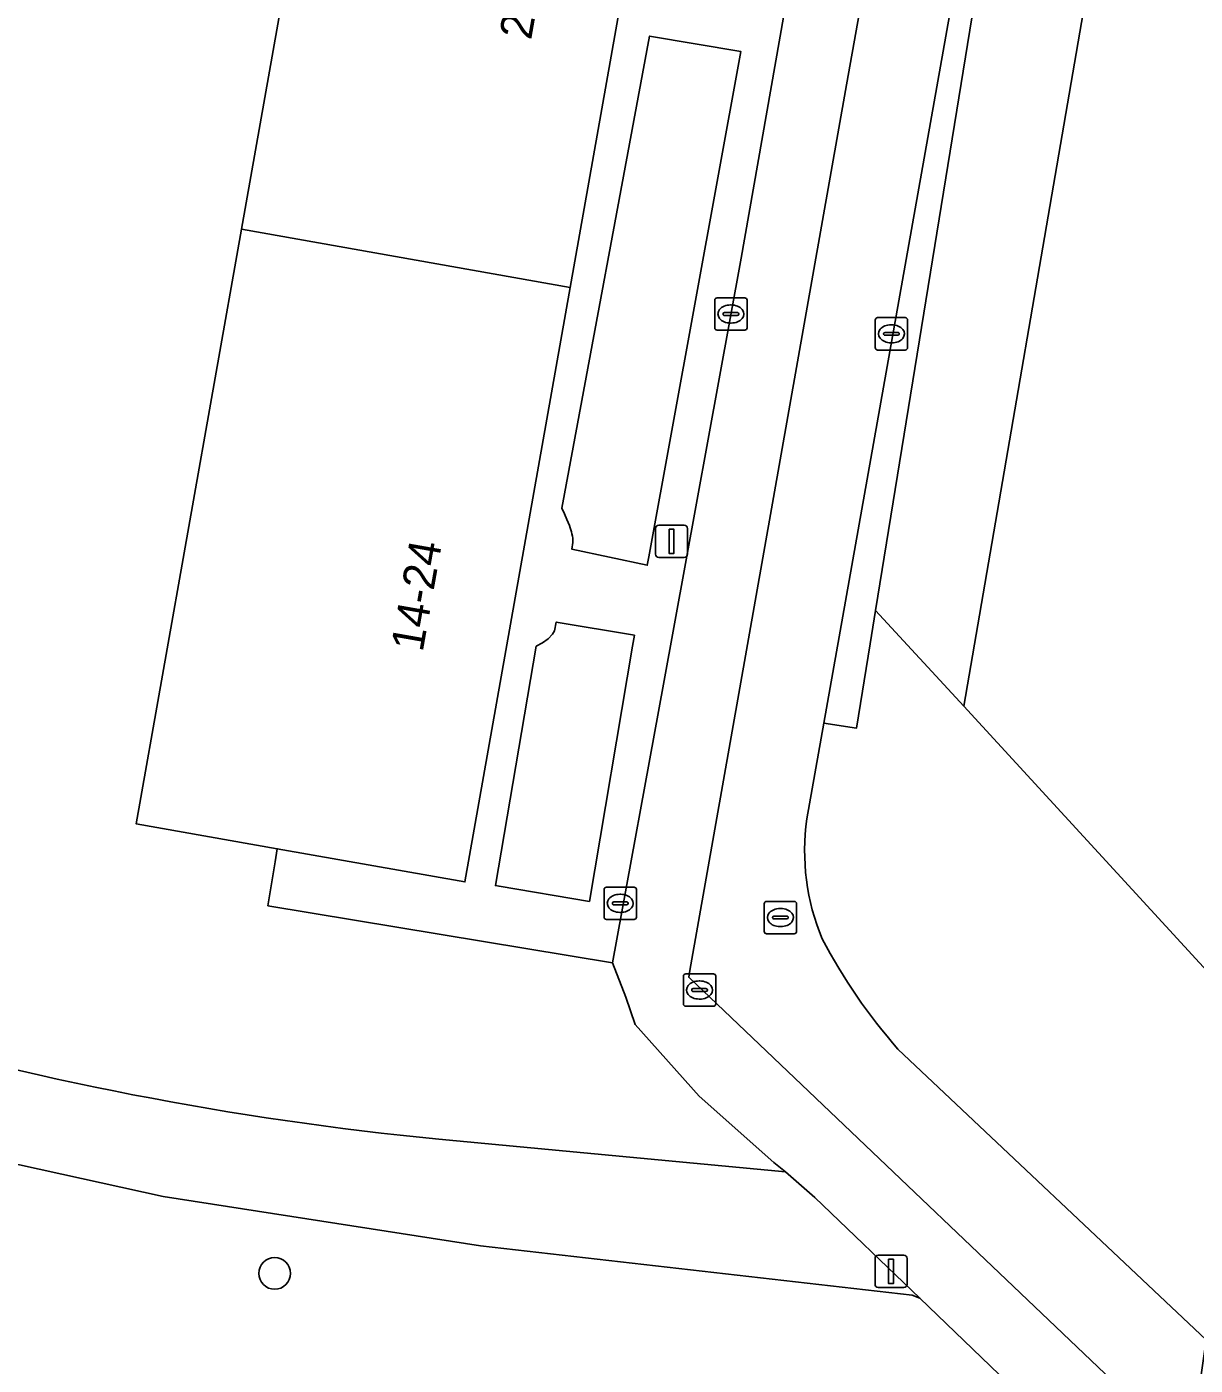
# Model space of a CAD drawing. Extents: x 161402 to 161933, y 381647 to 382315.
# Drawn here: x 161750.87 to 161786.96, y 381873.54 to 381914.91 of the extents above; entities that cross this region are included whole.
import ezdxf

# ---------------------------------------------------------------- set-up
doc = ezdxf.new("R2010")
doc.units = 0
for name, color, linetype in [('IMGEO_Boom', 7, 'Continuous'), ('IMGEO_Groenvoorziening', 7, 'Continuous'), ('IMGEO_Haag', 7, 'Continuous'), ('IMGEO_Kolk', 7, 'Continuous'), ('IMGEO_Lichtmast', 7, 'Continuous'), ('IMGEO_Pand', 7, 'Continuous'), ('IMGEO_Pand_nummerreeks', 7, 'Continuous'), ('IMGEO_Parkeervlak_open', 7, 'Continuous'), ('IMGEO_Rijbaan_lokaal_open', 7, 'Continuous'), ('IMGEO_Rioolput', 7, 'Continuous'), ('IMGEO_Voetpad_gesloten', 7, 'Continuous'), ('IMGEO_Voetpad_open', 7, 'Continuous')]:
    doc.layers.add(name, color=color, linetype=linetype)

msp = doc.modelspace()

# ---------------------------------------------------------------- linework, layer by layer
at = {"layer": 'IMGEO_Boom'}
msp.add_circle((161758.532, 381876.381), 0.489, dxfattribs=at)
at = {"layer": 'IMGEO_Groenvoorziening'}
for points in [[(161794.921, 381938.465), (161786.816, 381934.618), (161779.814, 381893.915), (161788.716, 381884.216), (161790.718, 381897.39), (161795.348, 381935.098)], [(161768.961, 381885.978), (161758.322, 381887.744), (161758.545, 381889.099), (161758.611, 381889.504), (161754.257, 381890.274), (161757.508, 381908.649), (161760.759, 381927.025), (161770.911, 381925.228), (161771.029, 381925.951), (161771.159, 381926.744), (161771.362, 381926.92), (161776.174, 381926.042), (161776.84, 381929.749), (161763.83, 381931.916), (161761.561, 381932.294), (161753.635, 381933.615), (161746.013, 381890.587), (161744.878, 381884.178)], [(161772.929, 381914.138), (161770.112, 381914.616), (161767.404, 381900.027), (161767.48, 381899.856), (161767.556, 381899.683), (161767.635, 381899.489)], [(161767.745, 381898.97), (161767.706, 381898.766), (161770.039, 381898.265), (161770.086, 381898.523), (161772.929, 381914.138)], [(161779.814, 381893.915), (161777.092, 381896.872), (161776.924, 381895.837), (161776.5, 381893.226), (161775.497, 381893.39), (161774.971, 381890.426)], [(161777.78, 381883.315), (161787.303, 381874.33), (161787.345, 381874.628), (161788.716, 381884.216), (161779.814, 381893.915)], [(161763.6, 381880.53), (161774.308, 381879.519), (161773.952, 381879.809), (161771.638, 381881.858), (161769.662, 381884.07), (161769.381, 381884.923), (161768.961, 381885.978)]]:
    msp.add_lwpolyline(points, dxfattribs=at)
for points in [[(161782.918, 381932.741), (161783.2, 381934.478), (161782.784, 381934.462), (161775.497, 381893.39), (161776.5, 381893.226), (161776.924, 381895.837), (161777.092, 381896.872)], [(161779.814, 381893.915), (161786.816, 381934.618), (161782.918, 381932.741), (161777.092, 381896.872)], [(161769.643, 381896.103), (161767.228, 381896.511), (161767.174, 381896.24), (161767.115, 381896.132), (161766.978, 381895.991), (161766.803, 381895.872), (161766.609, 381895.764), (161765.347, 381888.366), (161765.464, 381888.346), (161768.253, 381887.875), (161769.585, 381895.761)], [(161778.453, 381875.613), (161778.225, 381875.706), (161764.885, 381877.23), (161755.085, 381878.76), (161745.595, 381880.853), (161744.038, 381871.1), (161758.643, 381868.683), (161758.758, 381869.329), (161762.157, 381868.723), (161762.42, 381870.235), (161785.953, 381866.129), (161786.294, 381868.013), (161785.266, 381869.061)]]:
    msp.add_lwpolyline(points, close=True, dxfattribs=at)
for centre, radius, start, end in [((161766.287, 381898.932), 1.458, 1.4862, 22.4469), ((161781.898, 381889.424), 6.999, 171.766, 202.7426), ((161791.369, 381895.151), 18.022, 207.9024, 221.056), ((161773.213, 381979.731), 99.666, 253.48297, 264.46507)]:
    msp.add_arc(centre, radius, start, end, dxfattribs=at)
at = {"layer": 'IMGEO_Haag'}
msp.add_lwpolyline([(161782.918, 381932.741), (161783.2, 381934.478), (161782.784, 381934.462), (161775.497, 381893.39), (161776.5, 381893.226), (161776.924, 381895.837), (161777.092, 381896.872)], close=True, dxfattribs=at)
at = {"layer": 'IMGEO_Kolk'}
for p, q in [((161772.122, 381905.603), (161772.122, 381906.455)), ((161772.197, 381906.529), (161773.049, 381906.529)), ((161772.61, 381906.309), (161772.635, 381906.309)), ((161773.123, 381906.455), (161773.123, 381905.603)), ((161772.381, 381906.023), (161772.381, 381906.035)), ((161772.819, 381905.986), (161772.421, 381905.986)), ((161772.424, 381906.072), (161772.822, 381906.072)), ((161772.865, 381906.035), (161772.865, 381906.023)), ((161777.155, 381905.916), (161778.007, 381905.916)), ((161773.049, 381905.529), (161772.197, 381905.529)), ((161772.633, 381905.749), (161772.608, 381905.749)), ((161777.08, 381904.99), (161777.08, 381905.842)), ((161777.382, 381905.459), (161777.78, 381905.459)), ((161777.568, 381905.696), (161777.593, 381905.696)), ((161778.081, 381905.842), (161778.081, 381904.99)), ((161777.339, 381905.41), (161777.339, 381905.422)), ((161777.777, 381905.373), (161777.379, 381905.373)), ((161777.591, 381905.136), (161777.566, 381905.136)), ((161777.823, 381905.422), (161777.823, 381905.41)), ((161778.007, 381904.916), (161777.155, 381904.916)), ((161768.704, 381887.392), (161768.704, 381888.244)), ((161768.779, 381888.318), (161769.631, 381888.318)), ((161769.192, 381888.098), (161769.217, 381888.098)), ((161769.705, 381888.244), (161769.705, 381887.392)), ((161768.963, 381887.812), (161768.963, 381887.824)), ((161769.401, 381887.775), (161769.003, 381887.775)), ((161769.006, 381887.861), (161769.404, 381887.861)), ((161769.447, 381887.824), (161769.447, 381887.812)), ((161773.651, 381886.952), (161773.651, 381887.804)), ((161773.726, 381887.878), (161774.578, 381887.878)), ((161774.652, 381887.804), (161774.652, 381886.952)), ((161769.631, 381887.318), (161768.779, 381887.318)), ((161769.215, 381887.538), (161769.19, 381887.538)), ((161773.91, 381887.372), (161773.91, 381887.384)), ((161774.348, 381887.335), (161773.95, 381887.335)), ((161773.953, 381887.421), (161774.351, 381887.421)), ((161774.139, 381887.658), (161774.164, 381887.658)), ((161774.394, 381887.384), (161774.394, 381887.372)), ((161774.578, 381886.878), (161773.726, 381886.878)), ((161774.162, 381887.098), (161774.137, 381887.098))]:
    msp.add_line(p, q, dxfattribs=at)
for points in [[(161772.122, 381905.603), (161772.122, 381906.455)], [(161772.197, 381906.529), (161773.049, 381906.529)], [(161773.123, 381906.455), (161773.123, 381905.603)], [(161777.155, 381905.916), (161778.007, 381905.916)], [(161773.049, 381905.529), (161772.197, 381905.529)], [(161777.08, 381904.99), (161777.08, 381905.842)], [(161778.081, 381905.842), (161778.081, 381904.99)], [(161778.007, 381904.916), (161777.155, 381904.916)], [(161768.704, 381887.392), (161768.704, 381888.244)], [(161768.779, 381888.318), (161769.631, 381888.318)], [(161769.705, 381888.244), (161769.705, 381887.392)], [(161773.651, 381886.952), (161773.651, 381887.804)], [(161773.726, 381887.878), (161774.578, 381887.878)], [(161774.652, 381887.804), (161774.652, 381886.952)], [(161769.631, 381887.318), (161768.779, 381887.318)], [(161774.578, 381886.878), (161773.726, 381886.878)]]:
    msp.add_lwpolyline(points, dxfattribs=at)
for centre, radius, start, end in [((161772.199, 381906.453), 0.0765, 91.552, 178.448), ((161772.199, 381906.453), 0.0765, 91.552, 178.448), ((161773.047, 381906.453), 0.0765, 1.552, 88.448), ((161773.047, 381906.453), 0.0765, 1.552, 88.448), ((161772.421, 381906.032), 0.0403, 85.8775, 175.7526), ((161772.418, 381906.022), 0.0366, 178.938, 274.7102), ((161772.822, 381906.029), 0.043, 264.8664, 352.4533), ((161772.826, 381906.034), 0.0386, 1.7309, 96.639), ((161777.157, 381905.84), 0.0765, 91.552, 178.448), ((161777.157, 381905.84), 0.0765, 91.552, 178.448), ((161778.005, 381905.84), 0.0765, 1.552, 88.448), ((161778.005, 381905.84), 0.0765, 1.552, 88.448), ((161772.199, 381905.605), 0.0765, 181.552, 268.448), ((161772.199, 381905.605), 0.0765, 181.552, 268.448), ((161773.047, 381905.605), 0.0765, 271.552, 358.448), ((161773.047, 381905.605), 0.0765, 271.552, 358.448), ((161777.379, 381905.419), 0.0403, 85.8775, 175.7526), ((161777.784, 381905.421), 0.0386, 1.7309, 96.639), ((161777.376, 381905.409), 0.0366, 178.938, 274.7102), ((161777.78, 381905.416), 0.043, 264.8664, 352.4533), ((161777.157, 381904.992), 0.0765, 181.552, 268.448), ((161777.157, 381904.992), 0.0765, 181.552, 268.448), ((161778.005, 381904.992), 0.0765, 271.552, 358.448), ((161778.005, 381904.992), 0.0765, 271.552, 358.448), ((161768.781, 381888.242), 0.0765, 91.552, 178.448), ((161768.781, 381888.242), 0.0765, 91.552, 178.448), ((161769.629, 381888.242), 0.0765, 1.552, 88.448), ((161769.629, 381888.242), 0.0765, 1.552, 88.448), ((161769.003, 381887.821), 0.0403, 85.8775, 175.7526), ((161769, 381887.811), 0.0366, 178.938, 274.7102), ((161769.404, 381887.818), 0.043, 264.8664, 352.4533), ((161769.408, 381887.823), 0.0386, 1.7309, 96.639), ((161773.728, 381887.802), 0.0765, 91.552, 178.448), ((161773.728, 381887.802), 0.0765, 91.552, 178.448), ((161774.576, 381887.802), 0.0765, 1.552, 88.448), ((161774.576, 381887.802), 0.0765, 1.552, 88.448), ((161768.781, 381887.394), 0.0765, 181.552, 268.448), ((161768.781, 381887.394), 0.0765, 181.552, 268.448), ((161769.629, 381887.394), 0.0765, 271.552, 358.448), ((161769.629, 381887.394), 0.0765, 271.552, 358.448), ((161773.95, 381887.381), 0.0403, 85.8775, 175.7526), ((161773.947, 381887.371), 0.0366, 178.938, 274.7102), ((161774.351, 381887.378), 0.043, 264.8664, 352.4533), ((161774.355, 381887.383), 0.0386, 1.7309, 96.639), ((161773.728, 381886.954), 0.0765, 181.552, 268.448), ((161773.728, 381886.954), 0.0765, 181.552, 268.448), ((161774.576, 381886.954), 0.0765, 271.552, 358.448), ((161774.576, 381886.954), 0.0765, 271.552, 358.448)]:
    msp.add_arc(centre, radius, start, end, dxfattribs=at)
for centre, major_axis, ratio, start_param, end_param in [((161772.609, 381906.029), (-0.387, 0.002), 0.722429, 4.712389, 7.853982), ((161772.634, 381906.029), (-0.39, 0.002), 0.717154, 1.570796, 4.712389), ((161777.567, 381905.416), (-0.387, 0.002), 0.722429, 4.712389, 7.853982), ((161777.592, 381905.416), (-0.39, 0.002), 0.717154, 1.570796, 4.712389), ((161769.191, 381887.818), (-0.387, 0.002), 0.722429, 4.712389, 7.853982), ((161769.216, 381887.818), (-0.39, 0.002), 0.717154, 1.570796, 4.712389), ((161774.138, 381887.378), (-0.387, 0.002), 0.722429, 4.712389, 7.853982), ((161774.163, 381887.378), (-0.39, 0.002), 0.717154, 1.570796, 4.712389)]:
    msp.add_ellipse(centre, major_axis=major_axis, ratio=ratio, start_param=start_param, end_param=end_param, dxfattribs=at)
at = {"layer": 'IMGEO_Lichtmast'}
for p, q in [((161770.292, 381898.604), (161770.292, 381899.404)), ((161770.292, 381899.404), (161770.292, 381898.604)), ((161770.392, 381899.504), (161771.182, 381899.504)), ((161771.182, 381899.504), (161770.392, 381899.504)), ((161771.282, 381899.404), (161771.282, 381898.604)), ((161771.282, 381898.604), (161771.282, 381899.404)), ((161771.182, 381898.504), (161770.392, 381898.504)), ((161770.392, 381898.504), (161771.182, 381898.504)), ((161777.173, 381876.944), (161777.963, 381876.944)), ((161777.963, 381876.944), (161777.173, 381876.944)), ((161777.073, 381876.044), (161777.073, 381876.844)), ((161777.073, 381876.844), (161777.073, 381876.044)), ((161778.063, 381876.844), (161778.063, 381876.044)), ((161778.063, 381876.044), (161778.063, 381876.844)), ((161777.963, 381875.944), (161777.173, 381875.944)), ((161777.173, 381875.944), (161777.963, 381875.944))]:
    msp.add_line(p, q, dxfattribs=at)
for points in [[(161770.712, 381899.379), (161770.862, 381899.379), (161770.862, 381898.629), (161770.712, 381898.629), (161770.712, 381899.379)], [(161777.493, 381876.819), (161777.643, 381876.819), (161777.643, 381876.069), (161777.493, 381876.069), (161777.493, 381876.819)]]:
    msp.add_lwpolyline(points, dxfattribs=at)
for centre, start, end in [((161770.392, 381899.404), 90, 180), ((161770.392, 381899.404), 90, 180), ((161771.182, 381899.404), 0, 90), ((161771.182, 381899.404), 360, 90), ((161770.392, 381898.604), 180, 270), ((161770.392, 381898.604), 180, 270), ((161771.182, 381898.604), 270, 0), ((161771.182, 381898.604), 270, 0), ((161777.173, 381876.844), 90, 180), ((161777.173, 381876.844), 90, 180), ((161777.963, 381876.844), 0, 90), ((161777.963, 381876.844), 360, 90), ((161777.173, 381876.044), 180, 270), ((161777.173, 381876.044), 180, 270), ((161777.963, 381876.044), 270, 0), ((161777.963, 381876.044), 270, 0)]:
    msp.add_arc(centre, 0.1, start, end, dxfattribs=at)
at = {"layer": 'IMGEO_Pand'}
for points in [[(161757.508, 381908.649), (161767.659, 381906.853), (161770.911, 381925.228), (161760.759, 381927.025)], [(161757.508, 381908.649), (161754.257, 381890.274), (161758.611, 381889.504), (161764.408, 381888.478), (161767.659, 381906.853)]]:
    msp.add_lwpolyline(points, close=True, dxfattribs=at)
at = {"layer": 'IMGEO_Parkeervlak_open'}
msp.add_lwpolyline([(161786.796, 381870.79), (161771.319, 381885.533), (161771.355, 381885.738), (161776.189, 381913.114), (161778.071, 381923.6), (161775.809, 381923.999), (161774.646, 381917.502), (161772.935, 381907.756), (161770.541, 381894.588), (161768.961, 381885.978), (161769.381, 381884.923), (161769.662, 381884.07), (161771.638, 381881.858), (161773.952, 381879.809), (161774.308, 381879.519), (161775.214, 381878.728), (161778.453, 381875.613), (161785.266, 381869.061), (161786.294, 381868.013)], close=True, dxfattribs=at)
at = {"layer": 'IMGEO_Rijbaan_lokaal_open'}
for points in [[(161782.784, 381934.462), (161784.762, 381945.37), (161780.082, 381947.784), (161779.9, 381946.775), (161782.071, 381946.391), (161778.29, 381924.974), (161776.054, 381925.369), (161775.809, 381923.999), (161778.071, 381923.6), (161776.189, 381913.114), (161771.355, 381885.738), (161771.319, 381885.533), (161786.796, 381870.79), (161787.303, 381874.33), (161777.78, 381883.315)], [(161774.971, 381890.426), (161775.497, 381893.39), (161782.784, 381934.462)]]:
    msp.add_lwpolyline(points, dxfattribs=at)
for centre, radius, start, end in [((161781.898, 381889.424), 6.999, 171.766, 202.7426), ((161791.369, 381895.151), 18.022, 207.9024, 221.056)]:
    msp.add_arc(centre, radius, start, end, dxfattribs=at)
at = {"layer": 'IMGEO_Rioolput'}
for p, q in [((161771.228, 381885.639), (161772.08, 381885.639)), ((161771.153, 381884.713), (161771.153, 381885.565)), ((161771.455, 381885.182), (161771.853, 381885.182)), ((161771.641, 381885.419), (161771.666, 381885.419)), ((161772.154, 381885.565), (161772.154, 381884.713)), ((161771.412, 381885.133), (161771.412, 381885.145)), ((161771.85, 381885.096), (161771.452, 381885.096)), ((161771.664, 381884.859), (161771.639, 381884.859)), ((161771.896, 381885.145), (161771.896, 381885.133)), ((161772.08, 381884.639), (161771.228, 381884.639))]:
    msp.add_line(p, q, dxfattribs=at)
for points in [[(161771.228, 381885.639), (161772.08, 381885.639)], [(161771.153, 381884.713), (161771.153, 381885.565)], [(161772.154, 381885.565), (161772.154, 381884.713)], [(161772.08, 381884.639), (161771.228, 381884.639)]]:
    msp.add_lwpolyline(points, dxfattribs=at)
for centre, radius, start, end in [((161771.23, 381885.563), 0.0765, 91.552, 178.448), ((161771.23, 381885.563), 0.0765, 91.552, 178.448), ((161772.078, 381885.563), 0.0765, 1.552, 88.448), ((161772.078, 381885.563), 0.0765, 1.552, 88.448), ((161771.452, 381885.142), 0.0403, 85.8775, 175.7526), ((161771.857, 381885.144), 0.0386, 1.7309, 96.639), ((161771.449, 381885.132), 0.0366, 178.938, 274.7102), ((161771.853, 381885.139), 0.043, 264.8664, 352.4533), ((161771.23, 381884.715), 0.0765, 181.552, 268.448), ((161771.23, 381884.715), 0.0765, 181.552, 268.448), ((161772.078, 381884.715), 0.0765, 271.552, 358.448), ((161772.078, 381884.715), 0.0765, 271.552, 358.448)]:
    msp.add_arc(centre, radius, start, end, dxfattribs=at)
for centre, major_axis, ratio, start_param, end_param in [((161771.64, 381885.139), (-0.387, 0.002), 0.722429, 4.712389, 7.853982), ((161771.665, 381885.139), (-0.39, 0.002), 0.717154, 1.570796, 4.712389)]:
    msp.add_ellipse(centre, major_axis=major_axis, ratio=ratio, start_param=start_param, end_param=end_param, dxfattribs=at)
at = {"layer": 'IMGEO_Voetpad_gesloten'}
msp.add_lwpolyline([(161741.245, 381881.98), (161744.341, 381881.177), (161745.595, 381880.853), (161755.085, 381878.76), (161764.885, 381877.23), (161778.225, 381875.706), (161778.453, 381875.613), (161775.214, 381878.728), (161774.308, 381879.519), (161763.6, 381880.53)], dxfattribs=at)
msp.add_arc((161773.213, 381979.731), 99.666, 253.48297, 264.46507, dxfattribs=at)
at = {"layer": 'IMGEO_Voetpad_open'}
for points in [[(161772.935, 381907.756), (161774.646, 381917.502), (161775.809, 381923.999), (161776.054, 381925.369), (161776.174, 381926.042), (161771.362, 381926.92), (161771.159, 381926.744), (161771.029, 381925.951), (161770.911, 381925.228), (161767.659, 381906.853), (161764.408, 381888.478), (161758.611, 381889.504), (161758.545, 381889.099), (161758.322, 381887.744), (161768.961, 381885.978), (161770.541, 381894.588)], [(161767.228, 381896.511), (161769.643, 381896.103), (161769.585, 381895.761), (161768.253, 381887.875), (161765.464, 381888.346), (161765.347, 381888.366), (161766.609, 381895.764), (161766.803, 381895.872), (161766.978, 381895.991), (161767.115, 381896.132), (161767.174, 381896.24)]]:
    msp.add_lwpolyline(points, close=True, dxfattribs=at)
for points in [[(161767.404, 381900.027), (161770.112, 381914.616), (161772.929, 381914.138), (161770.086, 381898.523), (161770.039, 381898.265), (161767.706, 381898.766), (161767.745, 381898.97)], [(161767.635, 381899.489), (161767.556, 381899.683), (161767.48, 381899.856), (161767.404, 381900.027)]]:
    msp.add_lwpolyline(points, dxfattribs=at)
msp.add_arc((161766.287, 381898.932), 1.458, 1.4862, 22.4469, dxfattribs=at)

# ---------------------------------------------------------------- texts
at = {"layer": 'IMGEO_Pand_nummerreeks'}
for s, p in [('2-12', (161766.449, 381914.474)), ('14-24', (161763.101, 381895.559))]:
    msp.add_text(s, height=1, rotation=79.9653, dxfattribs=at).set_placement(p)

doc.saveas('drawing.dxf')
